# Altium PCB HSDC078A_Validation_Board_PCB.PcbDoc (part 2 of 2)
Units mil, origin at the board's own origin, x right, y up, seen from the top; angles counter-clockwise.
Board outline 3100 x 3100 mil, 4 copper layers (L1-TOP, L2, L3, L4-BOT), stack 61.6 mil thick; 80 components, 31 nets, 179 pads, 275 vias.
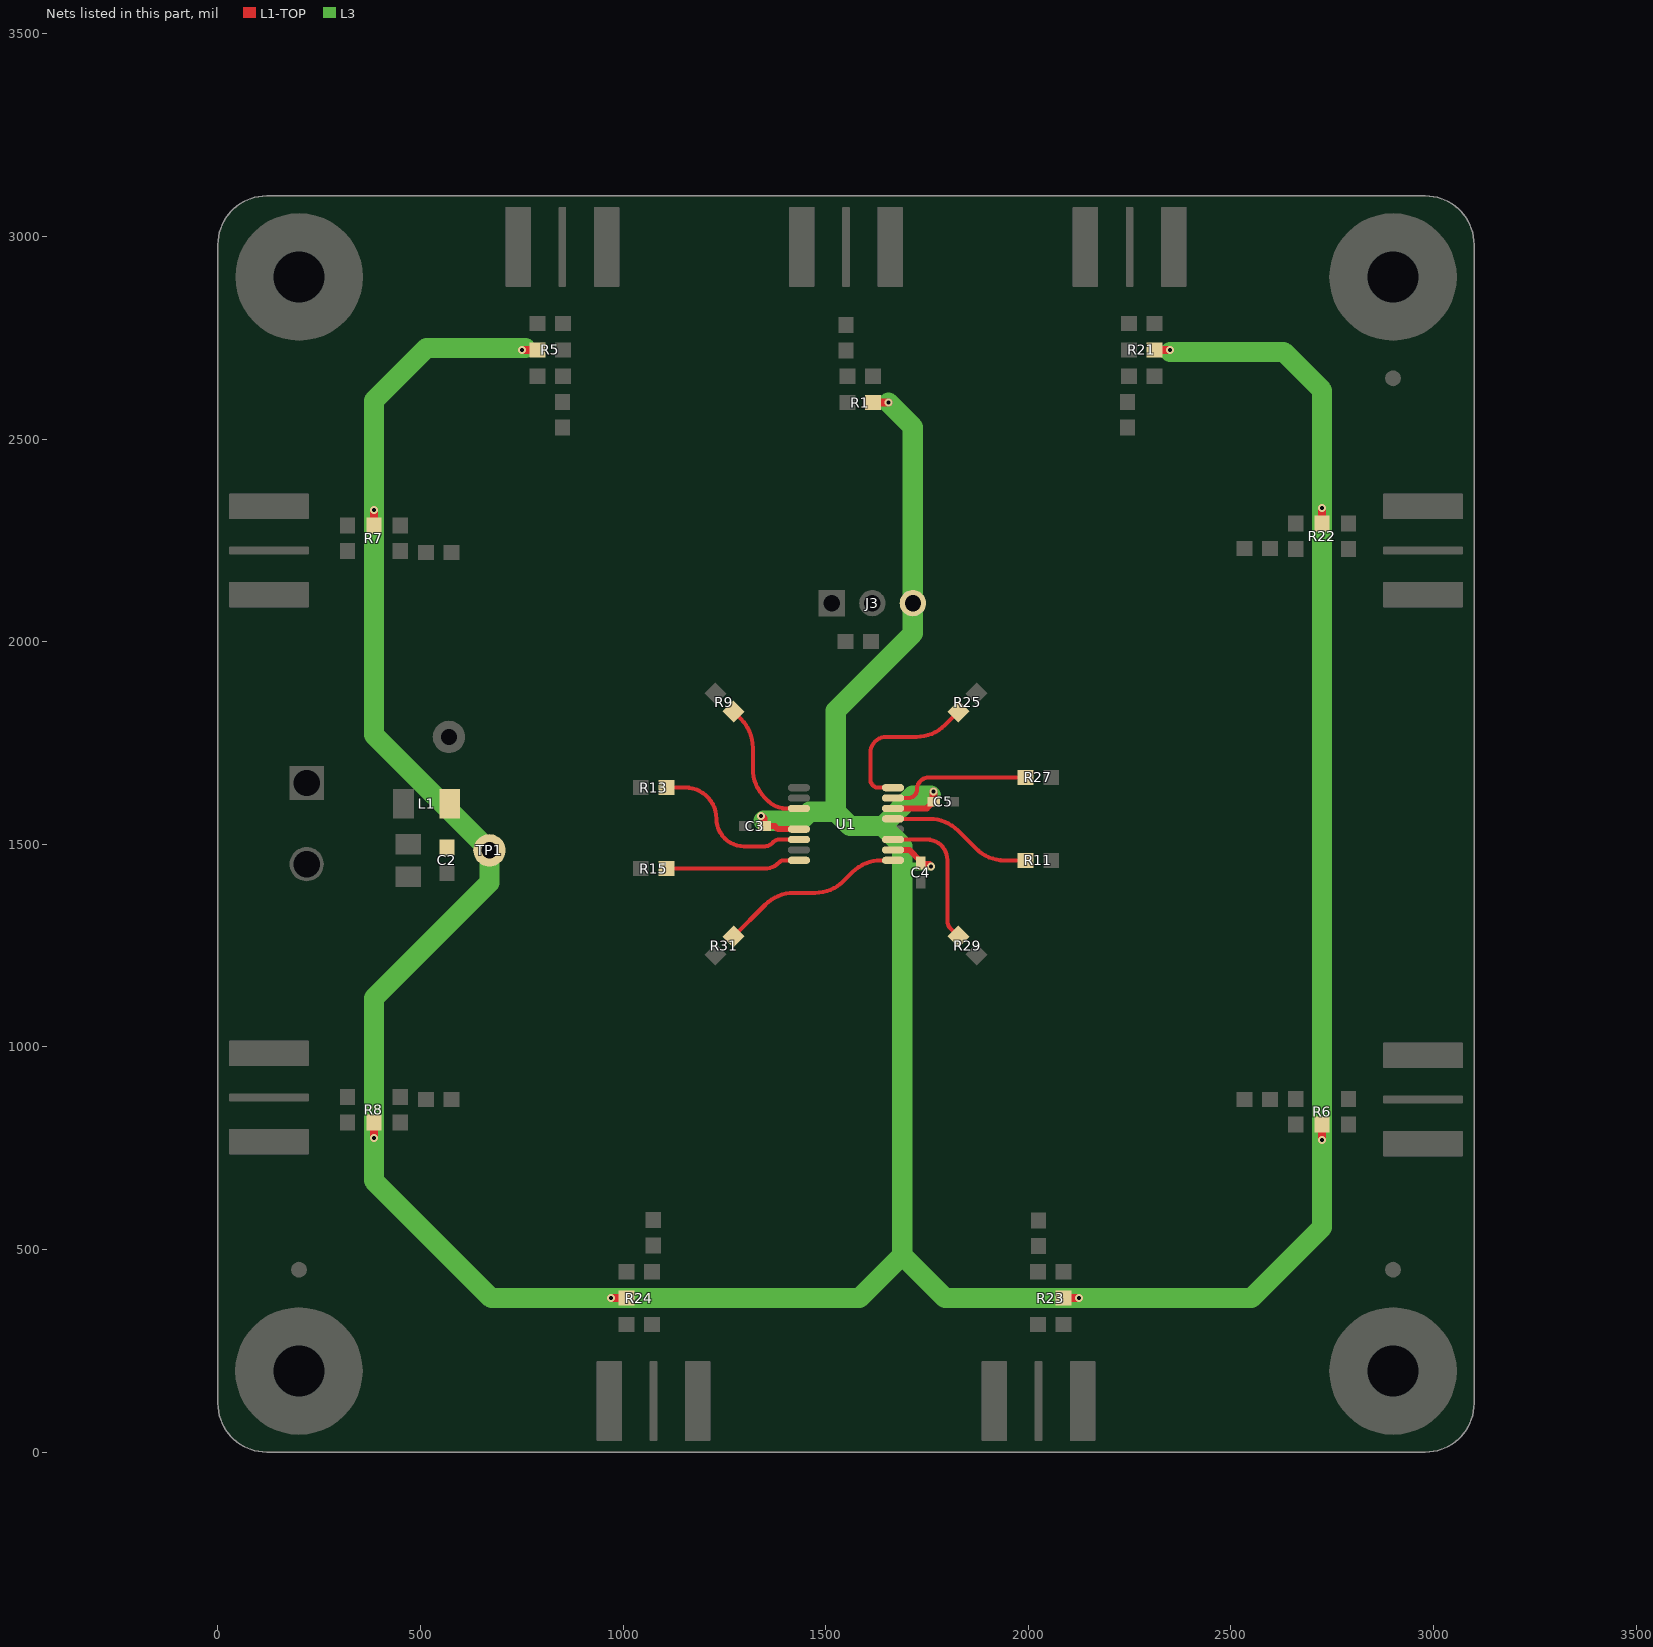
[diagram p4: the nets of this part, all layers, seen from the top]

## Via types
v1: diameter 20, hole 10, L1-TOP to L4-BOT, tented both sides, 275 vias

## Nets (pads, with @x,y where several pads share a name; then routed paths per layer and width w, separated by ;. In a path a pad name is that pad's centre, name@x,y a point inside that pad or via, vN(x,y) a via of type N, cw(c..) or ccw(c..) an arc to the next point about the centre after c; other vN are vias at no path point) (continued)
VDD: C2.1 C3.2 C4.2 C5.2 J3.3 L1.2 R1.1 R5.2 R6.2 R7.2 R8.2 R21.2 R22.2 R23.2 R24.2 TP1.1 U1.5 U1.10 U1.14 | length 11209.9
  L1-TOP w15: C3.2@1348.62,1545 1374.21,1545 1382.01,1537.2 U1.5@1433.86,1537.2 ; U1.10@1666.14,1486.02 1706.48,1486.02 1735,1457.5 C4.2@1735,1453.62 ; U1.14@1666.14,1588.39 1749.76,1588.39 C5.2@1766.38,1605
  L1-TOP w20: v1(385,775) R8.2@385,813.5 ; R7.2@385,2286.5 v1(385,2325) ; v1(750,2720) R5.2@788.5,2720 ; v1(970,380) R24.2@1008.5,380 ; v1(1340,1570) 1346,1564 1346,1547.62 C3.2@1348.62,1545 ; R1.1@1616.5,2590 v1(1655,2590) ; C4.2@1735,1453.62 1739.62,1449 1756,1449 v1(1760,1445) ; C5.2@1766.38,1605 v1(1766.38,1630) ; R23.2@2086.5,380 v1(2125,380) ; R21.2@2311.5,2720 v1(2350,2720) ; v1(2725,770) R6.2@2725,808.5 ; R22.2@2725,2291.5 v1(2725,2330)
  L3 w20: 1705,1442.5 1707.5,1445 v1(1760,1445)
  L3 w50: 758.98,2725 515,2725 385,2595 v1(385,2325) 385,1770 TP1.1@670,1485 670,1405 385,1120 v1(385,775) 385,670 675,380 1583,380 1689,486 ; 1347,1558 1438,1558 1460,1580 1525,1580 ; 1645,1550 1715,1620 1760,1620 ; v1(1655,2590) 1715,2530 J3.3@1715,2095 1715,2020 1525,1830 1525,1580 ; v1@2350,2715 2630,2715 2725,2620 v1(2725,2330) 2725,1045 ; 2725,945 2725,1045 ; 1525,1580 1560,1545 1645,1545 1645,1540 1689,1496 1689,486 ; 1689,486 1795,380 v1(2125,380) 2550,380 2725,555 v1(2725,770) 2725,1045
Y0: R9.1 U1.3 | length 328.6
  L1-TOP w10: R9.1@1272.27,1827.73 1290.71,1809.29 cw(c1220,1738.58) 1320,1738.58 1320,1686.42 ccw(c1420,1686.42) 1349.29,1615.71 1358.94,1606.06 ccw(c1401.61,1648.74) 1401.61,1588.39 U1.3@1433.86,1588.39
Y1: R25.1 U1.16 | length 394.9
  L1-TOP w10: U1.16@1666.14,1639.57 1630.67,1639.57 cw(c1630.67,1660.24) 1610,1660.24 1610,1725 cw(c1650,1725) 1650,1765 1723.58,1765 ccw(c1723.58,1865) 1794.29,1794.29 R25.1@1827.73,1827.73
Y2: R11.1 U1.13 | length 361.3
  L1-TOP w10: U1.13@1666.14,1562.8 1755.78,1562.8 cw(c1755.78,1462.8) 1826.49,1533.51 1870.71,1489.29 ccw(c1941.42,1560) 1941.42,1460 R11.1@1993.5,1460
Y3: R27.1 U1.15 | length 356.5
  L1-TOP w10: U1.15@1666.14,1613.98 1703.98,1613.98 ccw(c1703.98,1635) 1725,1635 cw(c1755,1635) 1755,1665 R27.1@1993.5,1665
Y4: R13.1 U1.6 | length 415
  L1-TOP w10: R13.1@1106.5,1640 1153.28,1640 cw(c1153.28,1563.28) 1230,1563.28 ccw(c1298.28,1563.28) 1250,1515 ccw(c1298.28,1563.28) 1298.28,1495 1350,1495 ccw(c1350,1519.14) 1367.07,1502.07 1370,1505 cw(c1385.97,1489.03) 1385.97,1511.61 U1.6@1433.86,1511.61
Y5: R29.1 U1.11 | length 362.1
  L1-TOP w10: U1.11@1666.14,1511.61 1749.89,1511.61 cw(c1749.89,1461.5) 1800,1461.5 1800,1310 ccw(c1824.14,1310) 1807.07,1292.93 R29.1@1827.73,1272.27
Y6: R15.1 U1.8 | length 332.8
  L1-TOP w10: R15.1@1106.5,1440 1348.79,1440 ccw(c1348.79,1491.21) 1385,1455 cw(c1398.12,1441.88) 1398.12,1460.43 U1.8@1433.86,1460.43
Y7: R31.1 U1.9 | length 458.9
  L1-TOP w10: R31.1@1272.27,1272.27 1350.71,1350.71 cw(c1421.42,1280) 1421.42,1380 1473.58,1380 ccw(c1473.58,1480) 1544.29,1409.29 1566.14,1431.14 cw(c1636.85,1360.43) 1636.85,1460.43 U1.9@1666.14,1460.43
pads on no net: FID1.1 FID2.1 FID3.1 H1.1 H2.1 H3.1 H4.1 H5.0 H6.0 H7.0 H8.0

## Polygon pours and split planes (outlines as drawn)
GND on L4-BOT "L4-BOT_GND_P002" (solid, pour order 2): 0,3100 0,0 3100,0 3100,3100
GND on L1-TOP "L1-TOP_GND_P004" (solid, pour order 4): 0,3100 0,-5 3100,-5 3100,3100
GND on L2 "L2_GND_P000" (solid, pour order 0): -0.47,3100 3100,3100 3100,0 0.57,0
GND on L3 "L3_GND_P008" (solid, pour order 8): -0.47,3100 3100,3100 3100,0 0.57,0

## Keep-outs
Keep-Out Layer:
  text ".Layer_Name" at 328.77,-1500.46 h60

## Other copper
L1-TOP:
  region net VDD: 615,1440 605,1450 590,1465 550,1465 535,1480 535,1630 550,1645 600,1645 715,1530 715,1450 705,1440
  region net NetC1_1: 505,1470 310,1470 170,1610 170,1690 180,1700 425,1700 505,1620
  pour cut-out: 550,1655.2 475.2,1655.2 475,1655 505,1625 505,1459.8 544.8,1459.8 550,1465
  text ".Layer_Name" at 328.77,-1500.46 h60
L2:
  pour cut-out: 835,3074.51 835,2890 865,2890 865,3074.51
  pour cut-out: 1522.8,2690.02 1577.27,2690.02 1577.27,2809.98 1522.8,2809.98
  pour cut-out: 822.8,2496.57 877.27,2496.57 877.27,2616.54 822.8,2616.54
  pour cut-out: 2217.8,2496.57 2272.27,2496.57 2272.27,2616.54 2217.8,2616.54
  pour cut-out: 2505.02,2257.2 2505.02,2202.73 2624.98,2202.73 2624.98,2257.2
  pour cut-out: 2505.02,897.2 2505.02,842.73 2624.98,842.73 2624.98,897.2
  pour cut-out: 2052.2,599.98 1997.73,599.98 1997.73,480.02 2052.2,480.02
  pour cut-out: 1101.65,601.48 1047.18,601.48 1047.18,481.51 1101.65,481.51
  pour cut-out: 604.98,842.8 604.98,897.27 485.02,897.27 485.02,842.8
  pour cut-out: 604.98,2192.8 604.98,2247.27 485.02,2247.27 485.02,2192.8
  pour cut-out: 1134.98,1612.8 1134.98,1667.27 1015.02,1667.27 1015.02,1612.8
  pour cut-out: 1138.43,1412.8 1138.43,1467.27 1018.46,1467.27 1018.46,1412.8
  pour cut-out: 1965.02,1487.2 1965.02,1432.73 2084.98,1432.73 2084.98,1487.2
  pour cut-out: 1965.02,1692.2 1965.02,1637.73 2084.98,1637.73 2084.98,1692.2
  pour cut-out: 1273.13,1788.31 1188.31,1873.13 1226.82,1911.65 1311.65,1826.82
  pour cut-out: 1788.31,1826.87 1873.13,1911.69 1911.65,1873.18 1826.82,1788.35
  pour cut-out: 1826.87,1311.69 1911.69,1226.87 1873.18,1188.35 1788.35,1273.18
  pour cut-out: 1311.69,1273.13 1226.87,1188.31 1188.35,1226.82 1273.18,1311.65
  pour cut-out: 1535,3074.51 1535,2890 1565,2890 1565,3074.51
  pour cut-out: 2235,3074.51 2235,2890 2265,2890 2265,3074.51
  pour cut-out: 3074.51,2240 2890,2240 2890,2210 3074.51,2210
  pour cut-out: 3074.51,885 2890,885 2890,855 3074.51,855
  pour cut-out: 2040,25.49 2040,210 2010,210 2010,25.49
  pour cut-out: 1090,25.49 1090,210 1060,210 1060,25.49
  pour cut-out: 25.49,860 210,860 210,890 25.49,890
  pour cut-out: 25.49,2210 210,2210 210,2240 25.49,2240
  text ".Layer_Name" at 330.54,-1498.73 h60
L3:
  pour cut-out: 835,3074.51 835,2890 865,2890 865,3074.51
  pour cut-out: 1522.8,2690.02 1577.27,2690.02 1577.27,2809.98 1522.8,2809.98
  pour cut-out: 822.8,2496.57 877.27,2496.57 877.27,2616.54 822.8,2616.54
  pour cut-out: 2217.8,2496.57 2272.27,2496.57 2272.27,2616.54 2217.8,2616.54
  pour cut-out: 2505.02,2257.2 2505.02,2202.73 2624.98,2202.73 2624.98,2257.2
  pour cut-out: 2505.02,897.2 2505.02,842.73 2624.98,842.73 2624.98,897.2
  pour cut-out: 2052.2,599.98 1997.73,599.98 1997.73,480.02 2052.2,480.02
  pour cut-out: 1101.65,601.48 1047.18,601.48 1047.18,481.51 1101.65,481.51
  pour cut-out: 604.98,842.8 604.98,897.27 485.02,897.27 485.02,842.8
  pour cut-out: 604.98,2192.8 604.98,2247.27 485.02,2247.27 485.02,2192.8
  pour cut-out: 1134.98,1612.8 1134.98,1667.27 1015.02,1667.27 1015.02,1612.8
  pour cut-out: 1138.43,1412.8 1138.43,1467.27 1018.46,1467.27 1018.46,1412.8
  pour cut-out: 1965.02,1487.2 1965.02,1432.73 2084.98,1432.73 2084.98,1487.2
  pour cut-out: 1965.02,1692.2 1965.02,1637.73 2084.98,1637.73 2084.98,1692.2
  pour cut-out: 1273.13,1788.31 1188.31,1873.13 1226.82,1911.65 1311.65,1826.82
  pour cut-out: 1788.31,1826.87 1873.13,1911.69 1911.65,1873.18 1826.82,1788.35
  pour cut-out: 1826.87,1311.69 1911.69,1226.87 1873.18,1188.35 1788.35,1273.18
  pour cut-out: 1311.69,1273.13 1226.87,1188.31 1188.35,1226.82 1273.18,1311.65
  pour cut-out: 1535,3074.51 1535,2890 1565,2890 1565,3074.51
  pour cut-out: 2235,3074.51 2235,2890 2265,2890 2265,3074.51
  pour cut-out: 3074.51,2240 2890,2240 2890,2210 3074.51,2210
  pour cut-out: 3074.51,885 2890,885 2890,855 3074.51,855
  pour cut-out: 2040,25.49 2040,210 2010,210 2010,25.49
  pour cut-out: 1090,25.49 1090,210 1060,210 1060,25.49
  pour cut-out: 25.49,860 210,860 210,890 25.49,890
  pour cut-out: 25.49,2210 210,2210 210,2240 25.49,2240
  text ".Layer_Name" at 330.54,-1498.73 h60
L4-BOT:
  text ".Layer_Name" at 328.77,-1500.46 h60

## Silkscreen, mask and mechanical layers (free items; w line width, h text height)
Top Overlay:
  text "Y0" at 910,2620 h120
  text "CLK_IN" at 1120,2620 h120
  text "Y1" at 2040,2615 h120
  text "GND" at 1550,2165 h120 r90
  text "1G" at 1650,2165 h120 r90
  text "VDD" at 1750,2165 h120 r90
  text "Y4" at 475,2085 h120
  text "Y3" at 2515,2085 h120
  text "GND" at 450,1840 h120
  text "VDD" at 45,1785 h120
  text "VDD" at 645,1565 h120
  text "GND" at 45,1245 h120
  text "Y6" at 475,950 h120
  text "Y2" at 2520,950 h120
  text "HSDC078A" at 1360,725 h72.83
  text "LMK1C1104EVM" at 1355,655 h72.83
  text "Y7" at 1175,390 h120
  text "Y5" at 1790,390 h120
  text ".Layer_Name" at 328.77,-1500.46 h60
Bottom Overlay:
  text ".Layer_Name" at 328.77,-1500.46 h60
Top Paste:
  text ".Layer_Name" at 327,-1502.19 h60
Bottom Paste:
  text ".Layer_Name" at 327,-1502.19 h60
Top Solder:
  text ".Layer_Name" at 327,-1502.19 h60
  text ".Layer_Name" at 327,-1502.19 h60
Bottom Solder:
  text ".Layer_Name" at 327,-1502.19 h60
Drill Guide:
  text ".Layer_Name" at 328.77,-1500.46 h60
M1 Board Outline:
  the board outline again, w10
  text ".Layer_Name" at 328.77,-1500.46 h60
M2 Board Dimensions:
  rectangle: -125,-1043.7 250,-918.7
  rectangle: -250,-918.7 -125,-793.7
  lines w7: -250,-918.7 750,-918.7 ; -125,-1043.7 -125,-793.7 ; 0,-1043.7 0,-793.7 ; 250,-1043.7 250,-793.7 ; 500,-1043.7 500,-793.7 ; -250,-1043.7 -250,-793.7 750,-793.7 750,-1043.7 -250,-1043.7
  text ".Layer_Name" at 327,-1502.19 h60
M3 3D STEP Top:
  text ".Layer_Name" at 327,-1502.19 h60
M4 3D STEP Bottom:
  text ".Layer_Name" at 327,-1502.19 h60
M5 Assembly Top:
  lines w10: -542,-1573.87 6058,-1573.87 ; -542,-1370.53 6060,-1370.53 ; -542,-1167.2 -542,-1777.2 3463,-1777.2 6060,-1777.2 6060,-1167.2 -541.5,-1167.2 -541.5,-1777.2 1034,-1777.2 ; 1923,-1777.2 1923,-1167.2 ; 3190,-1370.53 3190,-1167.2 ; 4030,-1370.53 4030,-1167.2 ; 4652,-1783.7 4652,-1580.87
  text "COMPONENTS MARKED 'DNP' SHOULD NOT BE POPULATED." at 903.5,-962.2 h60
  text "ASSEMBLY VARIANT:" at 903,-1077.7 h60
  text ".VariantName" at 1939,-1077.7 h60
  text "PCB VIEWED FROM TOP SIDE" at -478.5,-1299.37 h60
  text "BOARD #:" at 1998,-1299.37 h60
  text ".PRJ_Number" at 2543.5,-1299.37 h60
  text "REV:" at 3388,-1299.37 h60
  text ".PCB_Rev" at 3679.5,-1299.37 h60
  text "SVN REV:" at 4226,-1299.37 h60
  text ".VersionControl_RevNumber" at 4732,-1299.37 h60
  text "TID #:" at 1998,-1502.7 h60
  text ".TID" at 2543.5,-1502.7 h60
  text "PLOT NAME =" at -478.5,-1708.04 h60
  text ".plot_File_Name" at 327,-1708.04 h60
  text "GENERATED    :" at 2000,-1708.04 h60
  text ".Print_Date" at 2869.5,-1708.04 h60
  text ".Print_Time" at 3598.5,-1708.04 h60
  text "TEXAS INSTRUMENTS" at 4863,-1708.04 h60
M6 Assembly Bottom:
  lines w10: -542.5,-1371.03 6059.5,-1371.03 ; -540.5,-1574.37 6059.5,-1574.37 ; 865.5,-1784.2 865.5,-1581.37 ; 1487.5,-1371.03 1487.5,-1167.7 ; 2327.5,-1371.03 2327.5,-1167.7 ; 3594.5,-1777.7 3594.5,-1167.7 ; 4483.5,-1777.7 6059,-1777.7 6059,-1167.7 -542.5,-1167.7 -542.5,-1777.7 2054.5,-1777.7 6059.5,-1777.7 6059.5,-1167.7
  text "COMPONENTS MARKED 'DNP' SHOULD NOT BE POPULATED." at 5852,-961.7 h60
  text ".VariantName" at 4808,-1077.7 h60
  text "ASSEMBLY VARIANT:" at 5847,-1077.7 h60
  text ".VersionControl_RevNumber" at 785.5,-1299.87 h60
  text "SVN REV:" at 1291.5,-1299.87 h60
  text ".PCB_Rev" at 1838,-1299.87 h60
  text "REV:" at 2129.5,-1299.87 h60
  text ".PRJ_Number" at 2974,-1299.87 h60
  text "BOARD #:" at 3519.5,-1299.87 h60
  text "PCB VIEWED FROM BOTTOM SIDE" at 5996,-1299.87 h60
  text ".TID" at 2974,-1503.2 h60
  text "TID #:" at 3519.5,-1503.2 h60
  text "TEXAS INSTRUMENTS" at 654.5,-1708.54 h60
  text ".Print_Time" at 1919,-1708.54 h60
  text ".Print_Date" at 2648,-1708.54 h60
  text "GENERATED    :" at 3517.5,-1708.54 h60
  text ".plot_File_Name" at 5190.5,-1708.54 h60
  text "PLOT NAME =" at 5996,-1708.54 h60
M9 Title Sheet:
  drawing of 57 lines, arcs and shapes, not listed
  text "1" at 489.84,7392.8 h70
  text "2" at 2985.5,7392.8 h70
  text "3" at 5474.84,7392.8 h70
  text "4" at 7981.51,7392.8 h70
  text "5" at 10480.5,7392.8 h70
  text "6" at 12985.5,7392.8 h70
  text "A" at -666.5,6249.8 h70
  text "A" at 14133.5,6249.8 h70
  text "B" at -666.5,3869.8 h70
  text "B" at 14133.5,3869.8 h70
  text "C" at -666.5,1632.59 h70
  text "C" at 14133.5,1494.8 h70
  text "PROJECT TITLE:" at 11093.5,-366.2 h45
  text ".PRJ_Title" at 11143.5,-499.53 h70
  text "DESIGNED FOR:" at 11093.5,-667.2 h45
  text ".PRJ_Customer" at 11143.5,-807.2 h70
  text "D" at -666.5,-875.2 h70
  text "D" at 14133.5,-875.2 h70
  text "FILE NAME:" at 11093.5,-967.2 h45
  text ".PCB_File_Name_No_Path" at 11143.5,-1087.2 h70
  text "Texas Instruments (TI) and/or its licensors do not warrant the accuracy or completeness of this specification" at 6124,-1249.04 h45
  text "ENGINEER:" at 11093.5,-1257.2 h45
  text "LAYOUT BY:" at 12598.5,-1257.2 h45
  text "or any information contained therein. TI and/or its licensors do not warrant that this design will meet" at 6079.01,-1361.7 h45
  text ".PRJ_Engineer" at 11143.5,-1412.19 h70
  text ".PCB_Layout" at 12649,-1412.19 h70
  text "the specifications, will be suitable for your application or fit for any particular purpose, or will operate in" at 6079.01,-1474.37 h45
  text ".Layer_Name" at 327,-1502.19 h60
  text "ALTIUM DESIGNER VERSION:" at 12598.5,-1567.2 h45
  text "an implementation. TI and/or its licensors do not warrant that the design is production worthy. You should" at 6079.01,-1587.04 h45
  text "completely validate and test your design implementation to confirm the system functionality for your application." at 6124,-1699.7 h45
  text ".print_Scale" at 11143.5,-1700.53 h70
  text ".Application_BuildNumber" at 12649,-1700.53 h70
  text "1" at 489.84,-1907.2 h70
  text "2" at 2985.5,-1907.2 h70
  text "3" at 5474.84,-1907.2 h70
  text "4" at 7981.51,-1907.2 h70
  text "5" at 10480.5,-1907.2 h70
  text "6" at 12985.5,-1907.2 h70
M10 Fab Notes:
  drawing of 189 lines, arcs and shapes, not listed
  text "DESIGN INFORMATION" at 12132.02,5712.47 h60
  text "MIN. TRACK WIDTH:" at 11487.46,5580.35 h60
  text "10" at 12583.7,5580.35 h60
  text "MIL" at 12738.46,5580.35 h60
  text "MIN. CLEARANCE:" at 11487.46,5456.22 h60
  text "10" at 12523.7,5456.22 h60
  text "MIL" at 12738.46,5456.22 h60
  text "MIN. VIA PAD SIZE:" at 11487.46,5332.1 h60
  text "20" at 12553.71,5332.1 h60
  text "MIL" at 12738.46,5332.1 h60
  text "0.15mm (6MIL)" at 12182.46,5202.2 h60
  text "MINIMUM ANNULAR RING" at 11158.23,5193.97 h60
  text "EXTERNAL" at 12890.46,5193.97 h60
  text "PER" at 11358.23,5083.85 h60
  text "IPC-D-275 CLASS 2 LEVEL C" at 11578.23,5083.84 h60
  text "MIL, HOLES" at 13066.46,4983.37 h60
  text "+/-" at 12674,4974.78 h60
  text "+/-" at 13528,4974.78 h60
  text "REGISTRATION TOLERANCES:" at 11158.23,4973.72 h60
  text "METAL" at 12358,4973.72 h60
  text "5" at 12934.2,4973.72 h60
  text "3" at 13767.2,4973.72 h60
  text "MIL" at 13883.46,4973.72 h60
  text "HOLE SIZE TOLERANCE (UNLESS OTHERWISE SPECIFIED):" at 11158.23,4875.4 h60
  text "+/-" at 13528,4872.53 h60
  text "3" at 13767.2,4871.47 h60
  text "MIL" at 13883.46,4871.47 h60
  text "MATERIAL:" at 11083.46,4733.82 h60
  text "FR-4 High Tg" at 12069.9,4605.29 h60
  text "X" at 11925.46,4597.31 h60
  text "FR-408" at 11504.46,4592.79 h60
  text "OTHER" at 12992.46,4592.79 h60
  text "62 MIL (1.6mm) +/-10%" at 11824.56,4449.76 h60
  text "X" at 11704.46,4447.31 h60
  text "THICKNESS:" at 11158.23,4441.54 h60
  text "OTHER" at 13109.46,4441.54 h60
  text "TOLERANCE:" at 11158.23,4303.22 h60
  text "X" at 12006.46,4303.22 h60
  text "ANSI IPC-6012 TYPE 3 CLASS 2" at 12184.48,4303.22 h60
  text "OTHER +/-" at 12184.46,4159.03 h60
  text "BOW & TWIST:" at 11158.23,4013.84 h60
  text "X" at 12006.46,4013.84 h60
  text "ANSI IPC-6012 TYPE 3 CLASS 2" at 12184.48,4013.84 h60
  text "OTHER +/-" at 12184.46,3867.15 h60
  text "DRILLING:" at 11083.46,3736.53 h60
  text "NC_DRILL FILES" at 12844.46,3631.34 h60
  text "REFERENCE:" at 11158.23,3627.4 h60
  text "X" at 11815.46,3627.31 h60
  text "AS SHOWN" at 11993.46,3627.4 h60
  text "X" at 12716.46,3627.4 h60
  text "OTHER" at 13142.46,3485.15 h60
  text "PTH COPPER THICKNESS:" at 11157.91,3481.62 h60
  text "X" at 12297.14,3481.62 h60
  text "20-30 um" at 12425.14,3481.62 h60
  text "BOARD FINISH:" at 11083.46,3334.02 h60
  text "SILKSCREEN:" at 11238.68,3223.9 h60
  text "X" at 12196.46,3223.9 h60
  text "TOP" at 12313.46,3223.9 h60
  text "BOTTOM" at 12824.46,3223.9 h60
  text "SILKSCREEN COLOR:" at 11238.68,3068.71 h60
  text "X" at 12195.46,3068.71 h60
  text "WHITE" at 12313.46,3068.71 h60
  text "OTHER" at 12824.46,3068.71 h60
  text "X" at 12326.46,2925.26 h60
  text "GREEN" at 12444.46,2925.26 h60
  text "OTHER" at 13062.46,2925.26 h60
  text "SOLDER RESIST COLOR:" at 11238.68,2918.39 h60
  text "X" at 12326.46,2771.01 h60
  text "MATTE" at 12444.46,2771.01 h60
  text "SEMI-GLOSS" at 13062,2770.37 h60
  text "IMMERSION GOLD (ENIG)" at 12144.46,2598.24 h60
  text "ENEPIG" at 13482,2591.02 h60
  text "SURFACE FINISH:" at 11083.46,2590.02 h60
  text "X" at 11966.46,2590.02 h60
  text "IMM. TIN/SILVER OR EQUIV" at 11413,2452.7 h60
  text "OTHER" at 12844.46,2448.76 h60
  text "ARRAY/PANEL:" at 11083.46,2293.39 h60
  text "CUT AND TRIM PER M1 BOARD OUTLINE" at 12144.46,2285.16 h60
  text "PADS AT SMA CONNECTORS MUST EXTEND AS FAS TO THE EDGE OF THE BOARD AS PROCESSING ALLOWS TO ENSURE PROPER CIRCUIT PERFORMANCE." at 4360,2180 h60
  text "N.C. ROUTE" at 12144.46,2149.2 h60
  text "X" at 12832.46,2149.2 h60
  text "V. SCORE" at 13010.46,2149.2 h60
  text "CERTIFICATION:" at 11083.46,2020.07 h60
  text "MATERIALS AND WORKMANSHIP FOR ALL PCBS" at 11808.46,2020.07 h60
  text "TO MEET OR EXCEED THE REQUIREMENTS OF:" at 11808.46,1926.01 h60
  text "IMPEDANCE CONTROLLED TRACE TOLERANCE: 10%" at 4365,1885 h60
  text "X" at 11445.97,1797.38 h60
  text "ANSI IPC-A-600F CLASS ->" at 11573.96,1797.38 h60
  text "X" at 13221.97,1797.38 h60
  text "2" at 13331.96,1797.38 h60
  text "1" at 13016.96,1795.88 h60
  text "3" at 13685.96,1795.88 h60
  text "X" at 12257.97,1649.69 h60
  text "RoHS" at 12385.96,1649.69 h60
  text "OTHER" at 13030.36,1649.69 h60
  text "PER ORDER" at 13427.42,1649.69 h60
  text "ALL BOARDS MUST MEET OR EXCEED UL94-V0 REQUIREMENTS." at 11111,1495.87 h60
  text "PCB MUST BEAR THE UL94V-0 UL REGISTERED MATERIAL ID NUMBER" at 11111,1379.8 h60
  text "ADDITIONAL REQUIREMENTS:" at 11083.46,1210.38 h60
  text "MICROSECTION:" at 11158.23,1103.25 h60
  text "YES" at 12063.96,1103.25 h60
  text "REQUIRED" at 12925.46,958.92 h60
  text "BARE BOARD ELEC. TEST:" at 11158.23,956.06 h60
  text "NONE" at 12463.96,956.06 h60
  text "X" at 12807.46,956.06 h60
  text "PER ORDER" at 13517.46,956.06 h60
  text "XX MIL VIAS REQUIRE NON-CONDUCTIVE FILL AND PLANARIZE" at 11326.38,751.12 h59
  text "XX MIL VIAS REQUIRE CONDUCTIVE FILL AND PLANARIZE" at 11334.38,647.14 h60
  text "OUTER 10 MIL TRACES REQUIRE 50 OHM SINGLE-ENDED IMPEDANCE" at 11333.39,483.76 h57
  text "X" at 11217.46,482.69 h60
  text "LAYER 2 & 3 (INNER LAYERS) XX MIL WIDE, XX MIL SPACE / TRACES REQUIRE 100 OHM DIFFERENTIAL IMPEDANCE" at 11325.39,248.04 h60
  text ".Layer_Name" at 327,-1502.19 h60
M11 Gerber Information:
  lines w10: -542,-1573.87 6058,-1573.87 ; -542,-1370.53 6060,-1370.53 ; -542,-1167.2 -542,-1777.2 3463,-1777.2 6060,-1777.2 6060,-1167.2 -541.5,-1167.2 -541.5,-1777.2 1034,-1777.2 ; 1923,-1777.2 1923,-1167.2 ; 3190,-1370.53 3190,-1167.2 ; 4030,-1370.53 4030,-1167.2 ; 4652,-1783.7 4652,-1580.87
  text "ALL ARTWORK VIEWED FROM TOP SIDE" at -478.5,-1299.37 h60
  text "BOARD #:" at 1998,-1299.37 h60
  text ".PRJ_Number" at 2543.5,-1299.37 h60
  text "REV:" at 3388,-1299.37 h60
  text ".PCB_Rev" at 3679.5,-1299.37 h60
  text "SVN REV:" at 4226,-1299.37 h60
  text ".VersionControl_RevNumber" at 4732,-1299.37 h60
  text "LAYER NAME =" at -478.5,-1502.19 h60
  text "TID #:" at 1998,-1502.7 h60
  text ".TID" at 2543.5,-1502.7 h60
  text "PLOT NAME =" at -478.5,-1708.04 h60
  text ".plot_File_Name" at 327,-1708.04 h60
  text "GENERATED    :" at 2000,-1708.04 h60
  text ".Print_Date" at 2869.5,-1708.04 h60
  text ".Print_Time" at 3598.5,-1708.04 h60
  text "TEXAS INSTRUMENTS" at 4863,-1708.04 h60
M12 Stackup:
  drawing of 275 lines, arcs and shapes, not listed
  text "Layer" at 6422.5,6607.5 h60
  text "Name" at 6832.41,6607.5 h60
  text "Material" at 7762.16,6607.5 h60
  text "Thickness" at 8621.92,6607.5 h60
  text "Constant" at 9271.76,6607.5 h60
  text "Board Layer Stack" at 9841.62,6607.5 h60
  text "1" at 6422.5,6487.5 h60
  text "Top Overlay" at 6832.41,6487.5 h60
  text "2" at 6422.5,6367.5 h60
  text "Top Solder" at 6832.41,6367.5 h60
  text "Solder Resist" at 7762.16,6367.5 h60
  text "0.40mil" at 8621.92,6367.5 h60
  text "3.5" at 9271.76,6367.5 h60
  text "3" at 6422.5,6247.5 h60
  text "L1-TOP" at 6832.41,6247.5 h60
  text "Copper" at 7762.16,6247.5 h60
  text "1.40mil" at 8621.92,6247.5 h60
  text "4" at 6422.5,6127.5 h60
  text "Dielectric 1" at 6832.41,6127.5 h60
  text "FR-4 High TG" at 7762.16,6127.5 h60
  text "6.00mil" at 8621.92,6127.5 h60
  text "4.2" at 9271.76,6127.5 h60
  text "5" at 6422.5,6007.5 h60
  text "L2" at 6832.41,6007.5 h60
  text "Copper" at 7762.16,6007.5 h60
  text "1.40mil" at 8621.92,6007.5 h60
  text "6" at 6422.5,5887.5 h60
  text "Dielectric 2" at 6832.41,5887.5 h60
  text "FR-4 High TG" at 7762.16,5887.5 h60
  text "44.00mil" at 8621.92,5887.5 h60
  text "4.2" at 9271.76,5887.5 h60
  text "7" at 6422.5,5767.5 h60
  text "L3" at 6832.41,5767.5 h60
  text "Copper" at 7762.16,5767.5 h60
  text "1.40mil" at 8621.92,5767.5 h60
  text "8" at 6422.5,5647.5 h60
  text "Dielectric 3" at 6832.41,5647.5 h60
  text "FR-4 High TG" at 7762.16,5647.5 h60
  text "6.00mil" at 8621.92,5647.5 h60
  text "4.2" at 9271.76,5647.5 h60
  text "9" at 6422.5,5527.5 h60
  text "L4-BOT" at 6832.41,5527.5 h60
  text "Copper" at 7762.16,5527.5 h60
  text "1.40mil" at 8621.92,5527.5 h60
  text "10" at 6422.5,5407.5 h60
  text "Bottom Solder" at 6832.41,5407.5 h60
  text "Solder Resist" at 7762.16,5407.5 h60
  text "0.40mil" at 8621.92,5407.5 h60
  text "3.5" at 9271.76,5407.5 h60
  text "11" at 6422.5,5287.5 h60
  text "Bottom Overlay" at 6832.41,5287.5 h60
  text ".Layer_Name" at 327,-1502.19 h60
M13 Component Bodies Top:
  text ".Layer_Name" at 327,-1502.19 h60
M14 Component Bodies Bottom:
  text ".Layer_Name" at 327,-1502.19 h60
M15 Courtyards Top:
  text ".Layer_Name" at 327,-1502.19 h60
M16 Courtyards Bottom:
  text ".Layer_Name" at 327,-1502.19 h60
Drill Drawing:
  circle w10: c6469.42,4616.27 r32.37
  circle w10: c6469.42,4324.92 r19.42
  circle w10: c6469.42,4324.92 r32.37
  lines w10: 6437.05,4146.88 6469.42,4163.06 6501.79,4146.88 6485.61,4179.25 6501.79,4211.62 6469.42,4195.44 6437.05,4211.62 6453.24,4179.25 6437.05,4146.88 ; 6437.05,4438.23 6501.79,4438.23 6501.79,4502.97 6437.05,4502.97 6437.05,4438.23
  lines w12: 6378.89,4103.18 9931.75,4103.18 ; 6378.89,4685.87 9931.75,4685.87 ; 6774.75,3957.5 6774.75,4831.55 ; 7163.68,3957.5 7163.68,4831.55 ; 7909.3,3957.5 7909.3,4831.55 ; 8212.88,3957.5 8212.88,4831.55 ; 8652.4,3957.5 8652.4,4831.55 ; 9268.09,3957.5 9268.09,4831.55 ; 6378.89,3957.5 9931.75,3957.5 9931.75,4831.55 6378.89,4831.55 6378.89,3957.5
  text "Symbol" at 6466.3,4729.58 h84.39
  text "Quantity" at 6818.45,4729.58 h84.39
  text "Finished Hole Size" at 7207.38,4729.58 h84.39
  text "Plated" at 7953.01,4729.58 h84.39
  text "Hole Type" at 8256.58,4729.58 h84.39
  text "Drill Layer Pair" at 8696.1,4729.58 h84.39
  text "Hole Tolerance" at 9311.8,4729.58 h84.39
  text "275" at 6818.45,4583.9 h70.33
  text "10.00mil (0.254mm)" at 7207.38,4583.9 h70.33
  text "PTH" at 7953.01,4583.9 h70.33
  text "Round" at 8256.58,4583.9 h70.33
  text "L1-TOP - L4-BOT" at 8696.1,4583.9 h70.33
  text "5" at 6818.45,4438.23 h70.33
  text "40.00mil (1.016mm)" at 7207.38,4438.23 h70.33
  text "PTH" at 7953.01,4438.23 h70.33
  text "Round" at 8256.58,4438.23 h70.33
  text "L1-TOP - L4-BOT" at 8696.1,4438.23 h70.33
  text "2" at 6818.45,4292.55 h70.33
  text "64.96mil (1.650mm)" at 7207.38,4292.55 h70.33
  text "PTH" at 7953.01,4292.55 h70.33
  text "Round" at 8256.58,4292.55 h70.33
  text "L1-TOP - L4-BOT" at 8696.1,4292.55 h70.33
  text "4" at 6818.45,4146.88 h70.33
  text "125.98mil (3.200mm)" at 7207.38,4146.88 h70.33
  text "PTH" at 7953.01,4146.88 h70.33
  text "Round" at 8256.58,4146.88 h70.33
  text "L1-TOP - L4-BOT" at 8696.1,4146.88 h70.33
  text "286 Total" at 6818.45,4001.2 h70.33
  text ".Layer_Name" at 327,-1502.19 h60
Mechanical 17:
  text ".Layer_Name" at 327,-1502.19 h60
Mechanical 18:
  text ".Layer_Name" at 327,-1502.19 h60
Mechanical 19:
  text ".Layer_Name" at 327,-1502.19 h60

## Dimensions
120,0 to 120,3100 on M2 Board Dimensions
0,120 to 3100,120 on M2 Board Dimensions
-250,-1043.7 to 750,-1043.7 on M2 Board Dimensions
120,120 to -75,-245 on M2 Board Dimensions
